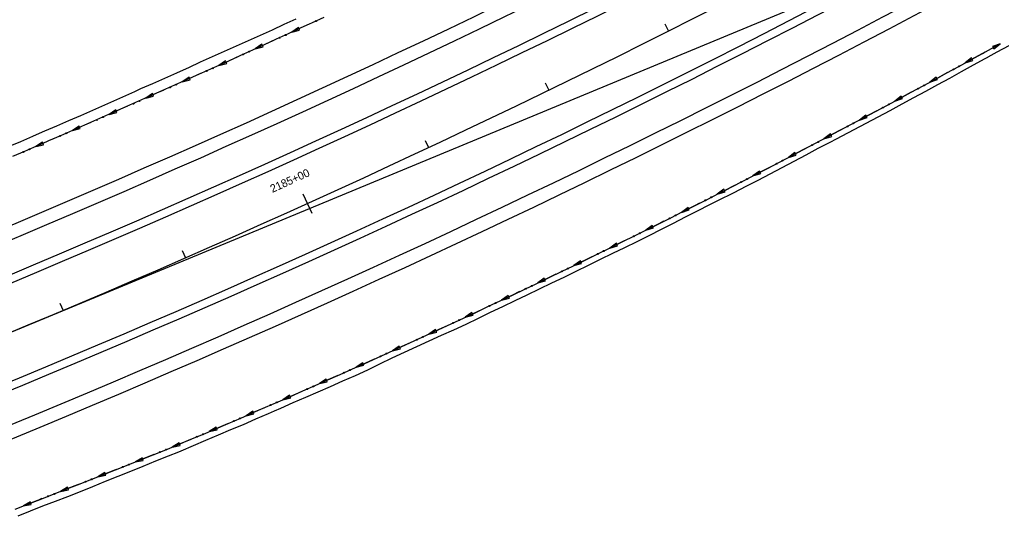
# Model space of a CAD drawing. Extents: x 1611108 to 1749517, y 619561 to 797725.
# Drawn here: x 1723874 to 1724610, y 768890 to 769262 of the extents above; entities that cross this region are included whole.
import ezdxf

# ---------------------------------------------------------------- set-up
doc = ezdxf.new("R2010")
doc.units = 0
for name, color, linetype in [('R_Ditch', 7, 'Continuous'), ('R_Horz Alg', 7, 'Continuous'), ('R_Horz Alg Annot', 7, 'Continuous'), ('R_Horz Alg Stationing', 7, 'Continuous'), ('R_Proposed Const Limits', 7, 'Continuous'), ('R_Proposed Road', 7, 'Continuous')]:
    doc.layers.add(name, color=color, linetype=linetype)

msp = doc.modelspace()

# ---------------------------------------------------------------- linework, layer by layer
at = {"layer": 'R_Ditch'}
for p, q in [((1724082.68, 769256.56), (1724077.67, 769253.1)), ((1724083.57, 769254.64), (1724082.68, 769256.56)), ((1724077.67, 769253.1), (1724083.57, 769254.64)), ((1724055.37, 769244.06), (1724050.35, 769240.61)), ((1724050.35, 769240.61), (1724056.25, 769242.14)), ((1724056.25, 769242.14), (1724055.37, 769244.06)), ((1724608.97, 769244.38), (1724603.2, 769242.44)), ((1724603.2, 769242.44), (1724604.21, 769240.59)), ((1724604.21, 769240.59), (1724608.97, 769244.38)), ((1724587.39, 769233.82), (1724582.64, 769230.01)), ((1724588.41, 769231.96), (1724587.39, 769233.82)), ((1724028.02, 769231.64), (1724022.99, 769228.21)), ((1724022.99, 769228.21), (1724028.9, 769229.72)), ((1724028.9, 769229.72), (1724028.02, 769231.64)), ((1724582.64, 769230.01), (1724588.41, 769231.96)), ((1724000.64, 769219.3), (1723995.6, 769215.88)), ((1724001.51, 769217.37), (1724000.64, 769219.3)), ((1724561.03, 769219.43), (1724556.26, 769215.64)), ((1724562.04, 769217.57), (1724561.03, 769219.43)), ((1723995.6, 769215.88), (1724001.51, 769217.37)), ((1724556.26, 769215.64), (1724562.04, 769217.57)), ((1723973.22, 769207.04), (1723968.17, 769203.64)), ((1723968.17, 769203.64), (1723974.08, 769205.11)), ((1723974.08, 769205.11), (1723973.22, 769207.04)), ((1724534.61, 769205.15), (1724529.83, 769201.38)), ((1724535.61, 769203.28), (1724534.61, 769205.15)), ((1724529.83, 769201.38), (1724535.61, 769203.28)), ((1723945.77, 769194.86), (1723940.71, 769191.47)), ((1723940.71, 769191.47), (1723946.62, 769192.93)), ((1723946.62, 769192.93), (1723945.77, 769194.86)), ((1724508.14, 769190.97), (1724503.34, 769187.22)), ((1724503.34, 769187.22), (1724509.13, 769189.1)), ((1724509.13, 769189.1), (1724508.14, 769190.97)), ((1723918.28, 769182.76), (1723913.21, 769179.38)), ((1723919.13, 769180.82), (1723918.28, 769182.76)), ((1723913.21, 769179.38), (1723919.13, 769180.82)), ((1724481.61, 769176.89), (1724476.79, 769173.15)), ((1724476.79, 769173.15), (1724482.59, 769175.02)), ((1724482.59, 769175.02), (1724481.61, 769176.89)), ((1723890.76, 769170.75), (1723885.67, 769167.4)), ((1723885.67, 769167.4), (1723891.59, 769168.8)), ((1723891.59, 769168.8), (1723890.76, 769170.75)), ((1724455.02, 769162.92), (1724450.19, 769159.2)), ((1724450.19, 769159.2), (1724456, 769161.04)), ((1724456, 769161.04), (1724455.02, 769162.92)), ((1724428.37, 769149.06), (1724423.53, 769145.37)), ((1724423.53, 769145.37), (1724429.34, 769147.18)), ((1724429.34, 769147.18), (1724428.37, 769149.06)), ((1724401.66, 769135.34), (1724396.79, 769131.67)), ((1724396.79, 769131.67), (1724402.62, 769133.46)), ((1724402.62, 769133.46), (1724401.66, 769135.34)), ((1724374.88, 769121.75), (1724369.99, 769118.1)), ((1724369.99, 769118.1), (1724375.83, 769119.86)), ((1724375.83, 769119.86), (1724374.88, 769121.75)), ((1724348.03, 769108.29), (1724343.13, 769104.67)), ((1724348.97, 769106.4), (1724348.03, 769108.29)), ((1724343.13, 769104.67), (1724348.97, 769106.4)), ((1724321.11, 769094.97), (1724316.2, 769091.37)), ((1724322.05, 769093.07), (1724321.11, 769094.97)), ((1724316.2, 769091.37), (1724322.05, 769093.07)), ((1724294.13, 769081.77), (1724289.2, 769078.2)), ((1724289.2, 769078.2), (1724295.06, 769079.87)), ((1724295.06, 769079.87), (1724294.13, 769081.77)), ((1724267.09, 769068.71), (1724262.14, 769065.17)), ((1724262.14, 769065.17), (1724268, 769066.81)), ((1724268, 769066.81), (1724267.09, 769068.71)), ((1724239.98, 769055.79), (1724235.01, 769052.26)), ((1724235.01, 769052.26), (1724240.89, 769053.87)), ((1724240.89, 769053.87), (1724239.98, 769055.79)), ((1724212.81, 769042.99), (1724207.82, 769039.49)), ((1724213.71, 769041.07), (1724212.81, 769042.99)), ((1724207.82, 769039.49), (1724213.71, 769041.07)), ((1724185.58, 769030.33), (1724180.57, 769026.86)), ((1724180.57, 769026.86), (1724186.46, 769028.41)), ((1724186.46, 769028.41), (1724185.58, 769030.33)), ((1724158.28, 769017.8), (1724153.26, 769014.35)), ((1724153.26, 769014.35), (1724159.16, 769015.88)), ((1724159.16, 769015.88), (1724158.28, 769017.8)), ((1724130.92, 769005.41), (1724125.88, 769001.99)), ((1724131.79, 769003.48), (1724130.92, 769005.41)), ((1724125.88, 769001.99), (1724131.79, 769003.48)), ((1724103.51, 768993.15), (1724098.45, 768989.75)), ((1724098.45, 768989.75), (1724104.36, 768991.22)), ((1724104.36, 768991.22), (1724103.51, 768993.15)), ((1724076.03, 768981.03), (1724070.96, 768977.66)), ((1724070.96, 768977.66), (1724076.88, 768979.09)), ((1724076.88, 768979.09), (1724076.03, 768981.03)), ((1724048.49, 768969.04), (1724043.4, 768965.69)), ((1724049.33, 768967.1), (1724048.49, 768969.04)), ((1724043.4, 768965.69), (1724049.33, 768967.1)), ((1724020.9, 768957.19), (1724015.79, 768953.87)), ((1724015.79, 768953.87), (1724021.73, 768955.24)), ((1724021.73, 768955.24), (1724020.9, 768957.19)), ((1723993.28, 768945.43), (1723988.11, 768942.21)), ((1723988.11, 768942.21), (1723994.07, 768943.47)), ((1723994.07, 768943.47), (1723993.28, 768945.43)), ((1723965.41, 768934.24), (1723960.22, 768931.04)), ((1723960.22, 768931.04), (1723966.19, 768932.28)), ((1723966.19, 768932.28), (1723965.41, 768934.24)), ((1723937.49, 768923.16), (1723932.3, 768919.98)), ((1723932.3, 768919.98), (1723938.27, 768921.19)), ((1723938.27, 768921.19), (1723937.49, 768923.16)), ((1723909.53, 768912.19), (1723904.33, 768909.03)), ((1723904.33, 768909.03), (1723910.3, 768910.22)), ((1723910.3, 768910.22), (1723909.53, 768912.19)), ((1723881.55, 768901.28), (1723876.34, 768898.12)), ((1723876.34, 768898.12), (1723882.31, 768899.31)), ((1723882.31, 768899.31), (1723881.55, 768901.28))]:
    msp.add_line(p, q, dxfattribs=at)
for points in [[(1724101.83, 769264.21), (1724093.08, 769260.18), (1724092.9, 769260.09), (1724083.96, 769255.98), (1724075.01, 769251.87), (1724066.06, 769247.78), (1724057.11, 769243.69), (1724048.16, 769239.61), (1724039.2, 769235.54), (1724030.23, 769231.48), (1724021.27, 769227.43), (1724012.29, 769223.38), (1724003.32, 769219.35), (1723994.34, 769215.32), (1723985.36, 769211.3), (1723976.37, 769207.29), (1723967.38, 769203.28), (1723962.87, 769201.28), (1723958.39, 769199.29), (1723949.39, 769195.3), (1723940.39, 769191.33), (1723931.38, 769187.36), (1723922.37, 769183.4), (1723913.36, 769179.45), (1723904.34, 769175.5), (1723895.32, 769171.57), (1723893.65, 769170.84), (1723886.29, 769167.67), (1723877.24, 769163.78), (1723868.2, 769159.91)], [(1724091.3, 769259.36), (1724083.96, 769255.98), (1724077.67, 769253.1)], [(1724091.34, 769259.37), (1724091.3, 769259.36)], [(1724064, 769246.84), (1724057.11, 769243.69), (1724050.35, 769240.61)], [(1724064.03, 769246.85), (1724064, 769246.84)], [(1724595.79, 769237.22), (1724597.69, 769238.25), (1724597.95, 769238.39), (1724604.72, 769242.07), (1724608.97, 769244.38)], [(1723870.37, 768895.8), (1723879.69, 768899.43), (1723889.01, 768903.06), (1723898.33, 768906.69), (1723907.65, 768910.32), (1723917.11, 768914.02), (1723926.57, 768917.73), (1723936.03, 768921.45), (1723945.49, 768925.19), (1723954.94, 768928.94), (1723964.38, 768932.7), (1723973.82, 768936.47), (1723983.26, 768940.26), (1723990.95, 768943.35), (1723992.68, 768944.08), (1724002.05, 768948.04), (1724011.41, 768952), (1724020.76, 768955.98), (1724030.11, 768959.98), (1724039.45, 768963.99), (1724048.78, 768968.02), (1724058.11, 768972.06), (1724062.76, 768974.08), (1724067.43, 768976.11), (1724076.75, 768980.19), (1724086.05, 768984.28), (1724095.35, 768988.38), (1724104.65, 768992.5), (1724113.94, 768996.64), (1724123.22, 769000.79), (1724132.49, 769004.95), (1724141.76, 769009.14), (1724151.02, 769013.33), (1724160.27, 769017.55), (1724169.51, 769021.77), (1724178.75, 769026.02), (1724187.98, 769030.28), (1724197.21, 769034.55), (1724206.42, 769038.84), (1724215.63, 769043.14), (1724224.83, 769047.46), (1724234.03, 769051.8), (1724243.22, 769056.15), (1724252.4, 769060.51), (1724261.57, 769064.9), (1724270.74, 769069.29), (1724279.9, 769073.7), (1724289.05, 769078.13), (1724298.19, 769082.57), (1724307.33, 769087.03), (1724316.46, 769091.5), (1724325.58, 769095.99), (1724334.7, 769100.49), (1724343.8, 769105.01), (1724352.9, 769109.54), (1724361.99, 769114.09), (1724371.07, 769118.65), (1724380.15, 769123.23), (1724389.22, 769127.82), (1724398.28, 769132.43), (1724404.39, 769135.55), (1724407.33, 769137.05), (1724416.38, 769141.69), (1724425.42, 769146.34), (1724434.44, 769151.01), (1724443.47, 769155.69), (1724452.48, 769160.39), (1724461.49, 769165.1), (1724470.48, 769169.83), (1724479.48, 769174.57), (1724484.33, 769177.13), (1724488.46, 769179.32), (1724497.44, 769184.08), (1724506.41, 769188.85), (1724515.38, 769193.64), (1724524.34, 769198.43), (1724533.29, 769203.24), (1724542.24, 769208.06), (1724551.18, 769212.89), (1724560.12, 769217.73), (1724569.05, 769222.59), (1724577.97, 769227.45), (1724586.88, 769232.33), (1724595.79, 769237.22)], [(1724036.66, 769234.39), (1724030.23, 769231.48), (1724022.99, 769228.21)], [(1724036.69, 769234.41), (1724036.66, 769234.39)], [(1724595.79, 769237.22), (1724586.88, 769232.33), (1724582.64, 769230.01)], [(1724009.28, 769222.03), (1724003.32, 769219.35), (1723995.6, 769215.88)], [(1724009.32, 769222.04), (1724009.28, 769222.03)], [(1724569.44, 769222.8), (1724569.05, 769222.59), (1724560.12, 769217.73), (1724556.26, 769215.64)], [(1724569.47, 769222.82), (1724569.44, 769222.8)], [(1723981.87, 769209.74), (1723976.37, 769207.29), (1723968.17, 769203.64)], [(1723981.91, 769209.76), (1723981.87, 769209.74)], [(1724543.03, 769208.49), (1724542.24, 769208.06), (1724533.29, 769203.24), (1724529.83, 769201.38)], [(1724543.07, 769208.51), (1724543.03, 769208.49)], [(1723954.43, 769197.54), (1723949.39, 769195.3), (1723940.71, 769191.47)], [(1723954.46, 769197.55), (1723954.43, 769197.54)], [(1724516.57, 769194.27), (1724515.38, 769193.64), (1724506.41, 769188.85), (1724503.34, 769187.22)], [(1724516.6, 769194.29), (1724516.57, 769194.27)], [(1723926.95, 769185.41), (1723922.37, 769183.4), (1723913.36, 769179.45), (1723913.21, 769179.38)], [(1723926.98, 769185.42), (1723926.95, 769185.41)], [(1724490.05, 769180.16), (1724488.46, 769179.32), (1724484.33, 769177.13), (1724479.48, 769174.57), (1724476.79, 769173.15)], [(1724490.09, 769180.18), (1724490.05, 769180.16)], [(1723899.43, 769173.36), (1723895.32, 769171.57), (1723893.65, 769170.84), (1723886.29, 769167.67), (1723885.66, 769167.4)], [(1723899.46, 769173.38), (1723899.43, 769173.36)], [(1724463.48, 769166.15), (1724461.49, 769165.1), (1724452.48, 769160.39), (1724450.19, 769159.2)], [(1724463.52, 769166.17), (1724463.48, 769166.15)], [(1724436.85, 769152.26), (1724434.44, 769151.01), (1724425.42, 769146.34), (1724423.53, 769145.37)], [(1724436.88, 769152.28), (1724436.85, 769152.26)], [(1724410.15, 769138.5), (1724407.33, 769137.05), (1724404.39, 769135.55), (1724398.28, 769132.43), (1724396.79, 769131.67)], [(1724410.19, 769138.51), (1724410.15, 769138.5)], [(1724383.38, 769124.87), (1724380.15, 769123.23), (1724371.07, 769118.65), (1724369.99, 769118.11)], [(1724383.42, 769124.88), (1724383.38, 769124.87)], [(1724356.55, 769111.37), (1724352.9, 769109.54), (1724343.8, 769105.01), (1724343.13, 769104.67)], [(1724356.58, 769111.38), (1724356.55, 769111.37)], [(1724329.65, 769098), (1724325.58, 769095.99), (1724316.46, 769091.5), (1724316.2, 769091.37)], [(1724329.69, 769098.01), (1724329.65, 769098)], [(1724302.69, 769084.76), (1724298.19, 769082.57), (1724289.2, 769078.2)], [(1724302.72, 769084.78), (1724302.69, 769084.76)], [(1724275.66, 769071.66), (1724270.74, 769069.29), (1724262.14, 769065.17)], [(1724275.69, 769071.68), (1724275.66, 769071.66)], [(1724248.56, 769058.69), (1724243.22, 769056.15), (1724235.01, 769052.26)], [(1724248.6, 769058.71), (1724248.56, 769058.69)], [(1724221.41, 769045.85), (1724215.63, 769043.14), (1724207.82, 769039.49)], [(1724221.44, 769045.87), (1724221.41, 769045.85)], [(1724194.19, 769033.15), (1724187.98, 769030.28), (1724180.57, 769026.86)], [(1724194.22, 769033.17), (1724194.19, 769033.15)], [(1724166.91, 769020.58), (1724160.27, 769017.55), (1724153.26, 769014.35)], [(1724166.94, 769020.6), (1724166.91, 769020.58)], [(1724139.56, 769008.15), (1724132.49, 769004.95), (1724125.88, 769001.99)], [(1724139.6, 769008.16), (1724139.56, 769008.15)], [(1724112.16, 768995.85), (1724104.65, 768992.5), (1724098.45, 768989.75)], [(1724112.19, 768995.86), (1724112.16, 768995.85)], [(1724084.69, 768983.68), (1724076.75, 768980.19), (1724070.96, 768977.66)], [(1724084.73, 768983.69), (1724084.69, 768983.68)], [(1724057.17, 768971.65), (1724048.78, 768968.02), (1724043.4, 768965.69)], [(1724057.21, 768971.66), (1724057.17, 768971.65)], [(1724029.59, 768959.75), (1724020.76, 768955.98), (1724015.79, 768953.87)], [(1724029.62, 768959.77), (1724029.59, 768959.75)], [(1724001.95, 768947.99), (1723992.68, 768944.08), (1723990.95, 768943.35), (1723988.11, 768942.21)], [(1724001.98, 768948.01), (1724001.95, 768947.99)], [(1723974.15, 768936.61), (1723973.82, 768936.47), (1723964.38, 768932.7), (1723960.22, 768931.04)], [(1723974.19, 768936.62), (1723974.15, 768936.61)], [(1723946.25, 768925.49), (1723945.49, 768925.19), (1723936.03, 768921.45), (1723932.3, 768919.98)], [(1723946.28, 768925.5), (1723946.25, 768925.49)], [(1723918.3, 768914.48), (1723917.11, 768914.02), (1723907.65, 768910.32), (1723904.33, 768909.03)], [(1723918.34, 768914.5), (1723918.3, 768914.48)], [(1723890.32, 768903.57), (1723889.01, 768903.06), (1723879.69, 768899.43), (1723876.34, 768898.12)], [(1723890.35, 768903.58), (1723890.32, 768903.57)]]:
    msp.add_lwpolyline(points, dxfattribs=at)
for centre in [(1724095.88, 769261.43), (1724068.58, 769248.89), (1724073.14, 769250.98), (1724041.25, 769236.43), (1724045.81, 769238.51), (1724018.45, 769226.12), (1724578.26, 769227.58), (1724013.88, 769224.06), (1724573.87, 769225.18), (1723986.47, 769211.76), (1723991.05, 769213.8), (1724547.47, 769210.84), (1724551.88, 769213.23), (1723959.03, 769199.54), (1723963.61, 769201.57), (1724521.02, 769196.61), (1724525.43, 769198.98), (1723936.14, 769189.42), (1723931.56, 769187.4), (1724494.51, 769182.48), (1724498.93, 769184.83), (1723904.05, 769175.34), (1723908.64, 769177.34), (1724467.95, 769168.46), (1724472.38, 769170.79), (1723876.48, 769163.42), (1723881.08, 769165.39), (1724441.32, 769154.54), (1724445.77, 769156.85), (1724414.64, 769140.76), (1724419.09, 769143.05), (1724387.88, 769127.1), (1724392.35, 769129.37), (1724365.54, 769115.83), (1724361.06, 769113.58), (1724338.66, 769102.42), (1724334.17, 769100.19), (1724307.22, 769086.93), (1724311.72, 769089.14), (1724280.2, 769073.81), (1724284.71, 769075.99), (1724253.11, 769060.82), (1724257.63, 769062.97), (1724230.5, 769050.09), (1724225.97, 769047.96), (1724198.76, 769035.23), (1724203.3, 769037.34), (1724171.49, 769022.64), (1724176.04, 769024.73), (1724148.72, 769012.25), (1724144.15, 769010.18), (1724116.76, 768997.86), (1724121.33, 768999.91), (1724089.3, 768985.67), (1724093.89, 768987.69), (1724066.38, 768975.62), (1724061.79, 768973.62), (1724034.22, 768961.7), (1724038.82, 768963.68), (1724006.59, 768949.92), (1724011.2, 768951.87), (1723978.83, 768938.44), (1723983.48, 768940.31), (1723950.93, 768927.31), (1723955.59, 768929.16), (1723922.99, 768916.28), (1723927.65, 768918.11), (1723895.01, 768905.36), (1723899.68, 768907.17)]:
    msp.add_circle(centre, 0.375, dxfattribs=at)
at = {"layer": 'R_Horz Alg'}
msp.add_arc((1720937.13, 776083.5), 7639.44, 292.5, 312.75, dxfattribs=at)
at = {"layer": 'R_Horz Alg Annot'}
msp.add_lwpolyline([(1723860.62, 769025.58), (1725121, 769547.65)], dxfattribs=at)
at = {"layer": 'R_Horz Alg Stationing'}
for points in [[(1724357.47, 769259.23), (1724360.15, 769253.87)], [(1724267.85, 769215.05), (1724270.46, 769209.65)], [(1724177.66, 769172.04), (1724180.2, 769166.6)], [(1724086.08, 769132.03), (1724092.69, 769117.46)], [(1723995.62, 769089.58), (1723998.03, 769084.08)], [(1723903.81, 769050.14), (1723906.15, 769044.61)]]:
    msp.add_lwpolyline(points, dxfattribs=at)
at = {"layer": 'R_Proposed Const Limits'}
for points in [[(1724080.77, 769262.9), (1724071.83, 769258.8), (1724062.89, 769254.7), (1724053.93, 769250.67), (1724044.97, 769246.62), (1724036.01, 769242.58), (1724027.04, 769238.55), (1724018.07, 769234.53), (1724009.1, 769230.51), (1724000.14, 769226.47), (1723993.99, 769223.73), (1723991.16, 769222.46), (1723982.17, 769218.48), (1723973.18, 769214.5), (1723964.19, 769210.52), (1723959.7, 769208.49), (1723955.23, 769206.48), (1723946.27, 769202.44), (1723937.3, 769198.42), (1723928.31, 769194.44), (1723919.31, 769190.48), (1723910.28, 769186.59), (1723901.25, 769182.7), (1723892.22, 769178.81), (1723890.55, 769178.08), (1723883.2, 769174.9), (1723874.17, 769171.01), (1723865.13, 769167.14)], [(1723872.44, 768890.8), (1723881.74, 768894.48), (1723891.06, 768898.1), (1723900.44, 768901.6), (1723909.74, 768905.28), (1723919.18, 768909.03), (1723928.63, 768912.8), (1723938.08, 768916.57), (1723947.51, 768920.37), (1723956.94, 768924.18), (1723966.37, 768928.01), (1723975.8, 768931.83), (1723985.24, 768935.63), (1723992.93, 768938.71), (1723994.67, 768939.44), (1724004.03, 768943.42), (1724013.37, 768947.44), (1724022.71, 768951.48), (1724032.09, 768955.42), (1724041.51, 768959.25), (1724050.84, 768963.31), (1724060.17, 768967.37), (1724064.81, 768969.41), (1724069.48, 768971.46), (1724078.81, 768975.51), (1724088.15, 768979.55), (1724097.49, 768983.6), (1724106.81, 768987.67), (1724116.1, 768991.81), (1724125.39, 768995.97), (1724134.66, 769000.15), (1724143.83, 769004.56), (1724153, 769008.97), (1724162.19, 769013.33), (1724171.44, 769017.56), (1724180.71, 769021.75), (1724189.97, 769025.95), (1724199.23, 769030.17), (1724208.49, 769034.39), (1724217.66, 769038.8), (1724226.83, 769043.2), (1724236, 769047.61), (1724245.15, 769052.04), (1724254.34, 769056.4), (1724263.52, 769060.78), (1724272.69, 769065.18), (1724281.86, 769069.59), (1724291.02, 769074.02), (1724300.15, 769078.49), (1724309.28, 769082.98), (1724318.4, 769087.48), (1724327.58, 769091.86), (1724336.73, 769096.31), (1724345.83, 769100.86), (1724354.9, 769105.46), (1724363.97, 769110.07), (1724373.03, 769114.69), (1724382.08, 769119.32), (1724391.18, 769123.87), (1724400.27, 769128.43), (1724406.4, 769131.51), (1724409.35, 769133.01), (1724418.42, 769137.62), (1724427.47, 769142.25), (1724436.5, 769146.93), (1724445.48, 769151.71), (1724454.44, 769156.53), (1724463.42, 769161.3), (1724472.4, 769166.08), (1724481.43, 769170.77), (1724486.3, 769173.3), (1724490.45, 769175.46), (1724499.46, 769180.18), (1724508.46, 769184.9), (1724517.45, 769189.65), (1724526.41, 769194.47), (1724535.36, 769199.29), (1724544.31, 769204.12), (1724553.25, 769208.97), (1724562.18, 769213.82), (1724571.11, 769218.69), (1724580.03, 769223.58), (1724588.91, 769228.52), (1724597.71, 769233.42), (1724597.8, 769233.47), (1724599.7, 769234.48), (1724599.97, 769234.63), (1724606.76, 769238.26), (1724615.72, 769243.07)]]:
    msp.add_lwpolyline(points, dxfattribs=at)
at = {"layer": 'R_Proposed Road'}
for p, q in [((1715977.87, 765723.64), (1723873.63, 768994.17)), ((1715980.17, 765718.1), (1723875.92, 768988.63)), ((1715989.35, 765695.93), (1723885.11, 768966.45)), ((1715993.18, 765686.69), (1723888.93, 768957.22))]:
    msp.add_line(p, q, dxfattribs=at)
for radius in [7565.44, 7575.44, 7599.44, 7605.44, 7673.44, 7679.44, 7703.44, 7713.44]:
    msp.add_arc((1720937.13, 776083.5), radius, 292.5, 312.75, dxfattribs=at)

# ---------------------------------------------------------------- texts
at = {"layer": 'R_Horz Alg Stationing'}
msp.add_text('2185+00', height=6, rotation=24.37011, dxfattribs=at).set_placement((1724063.15, 769132.62))

doc.saveas('drawing.dxf')
